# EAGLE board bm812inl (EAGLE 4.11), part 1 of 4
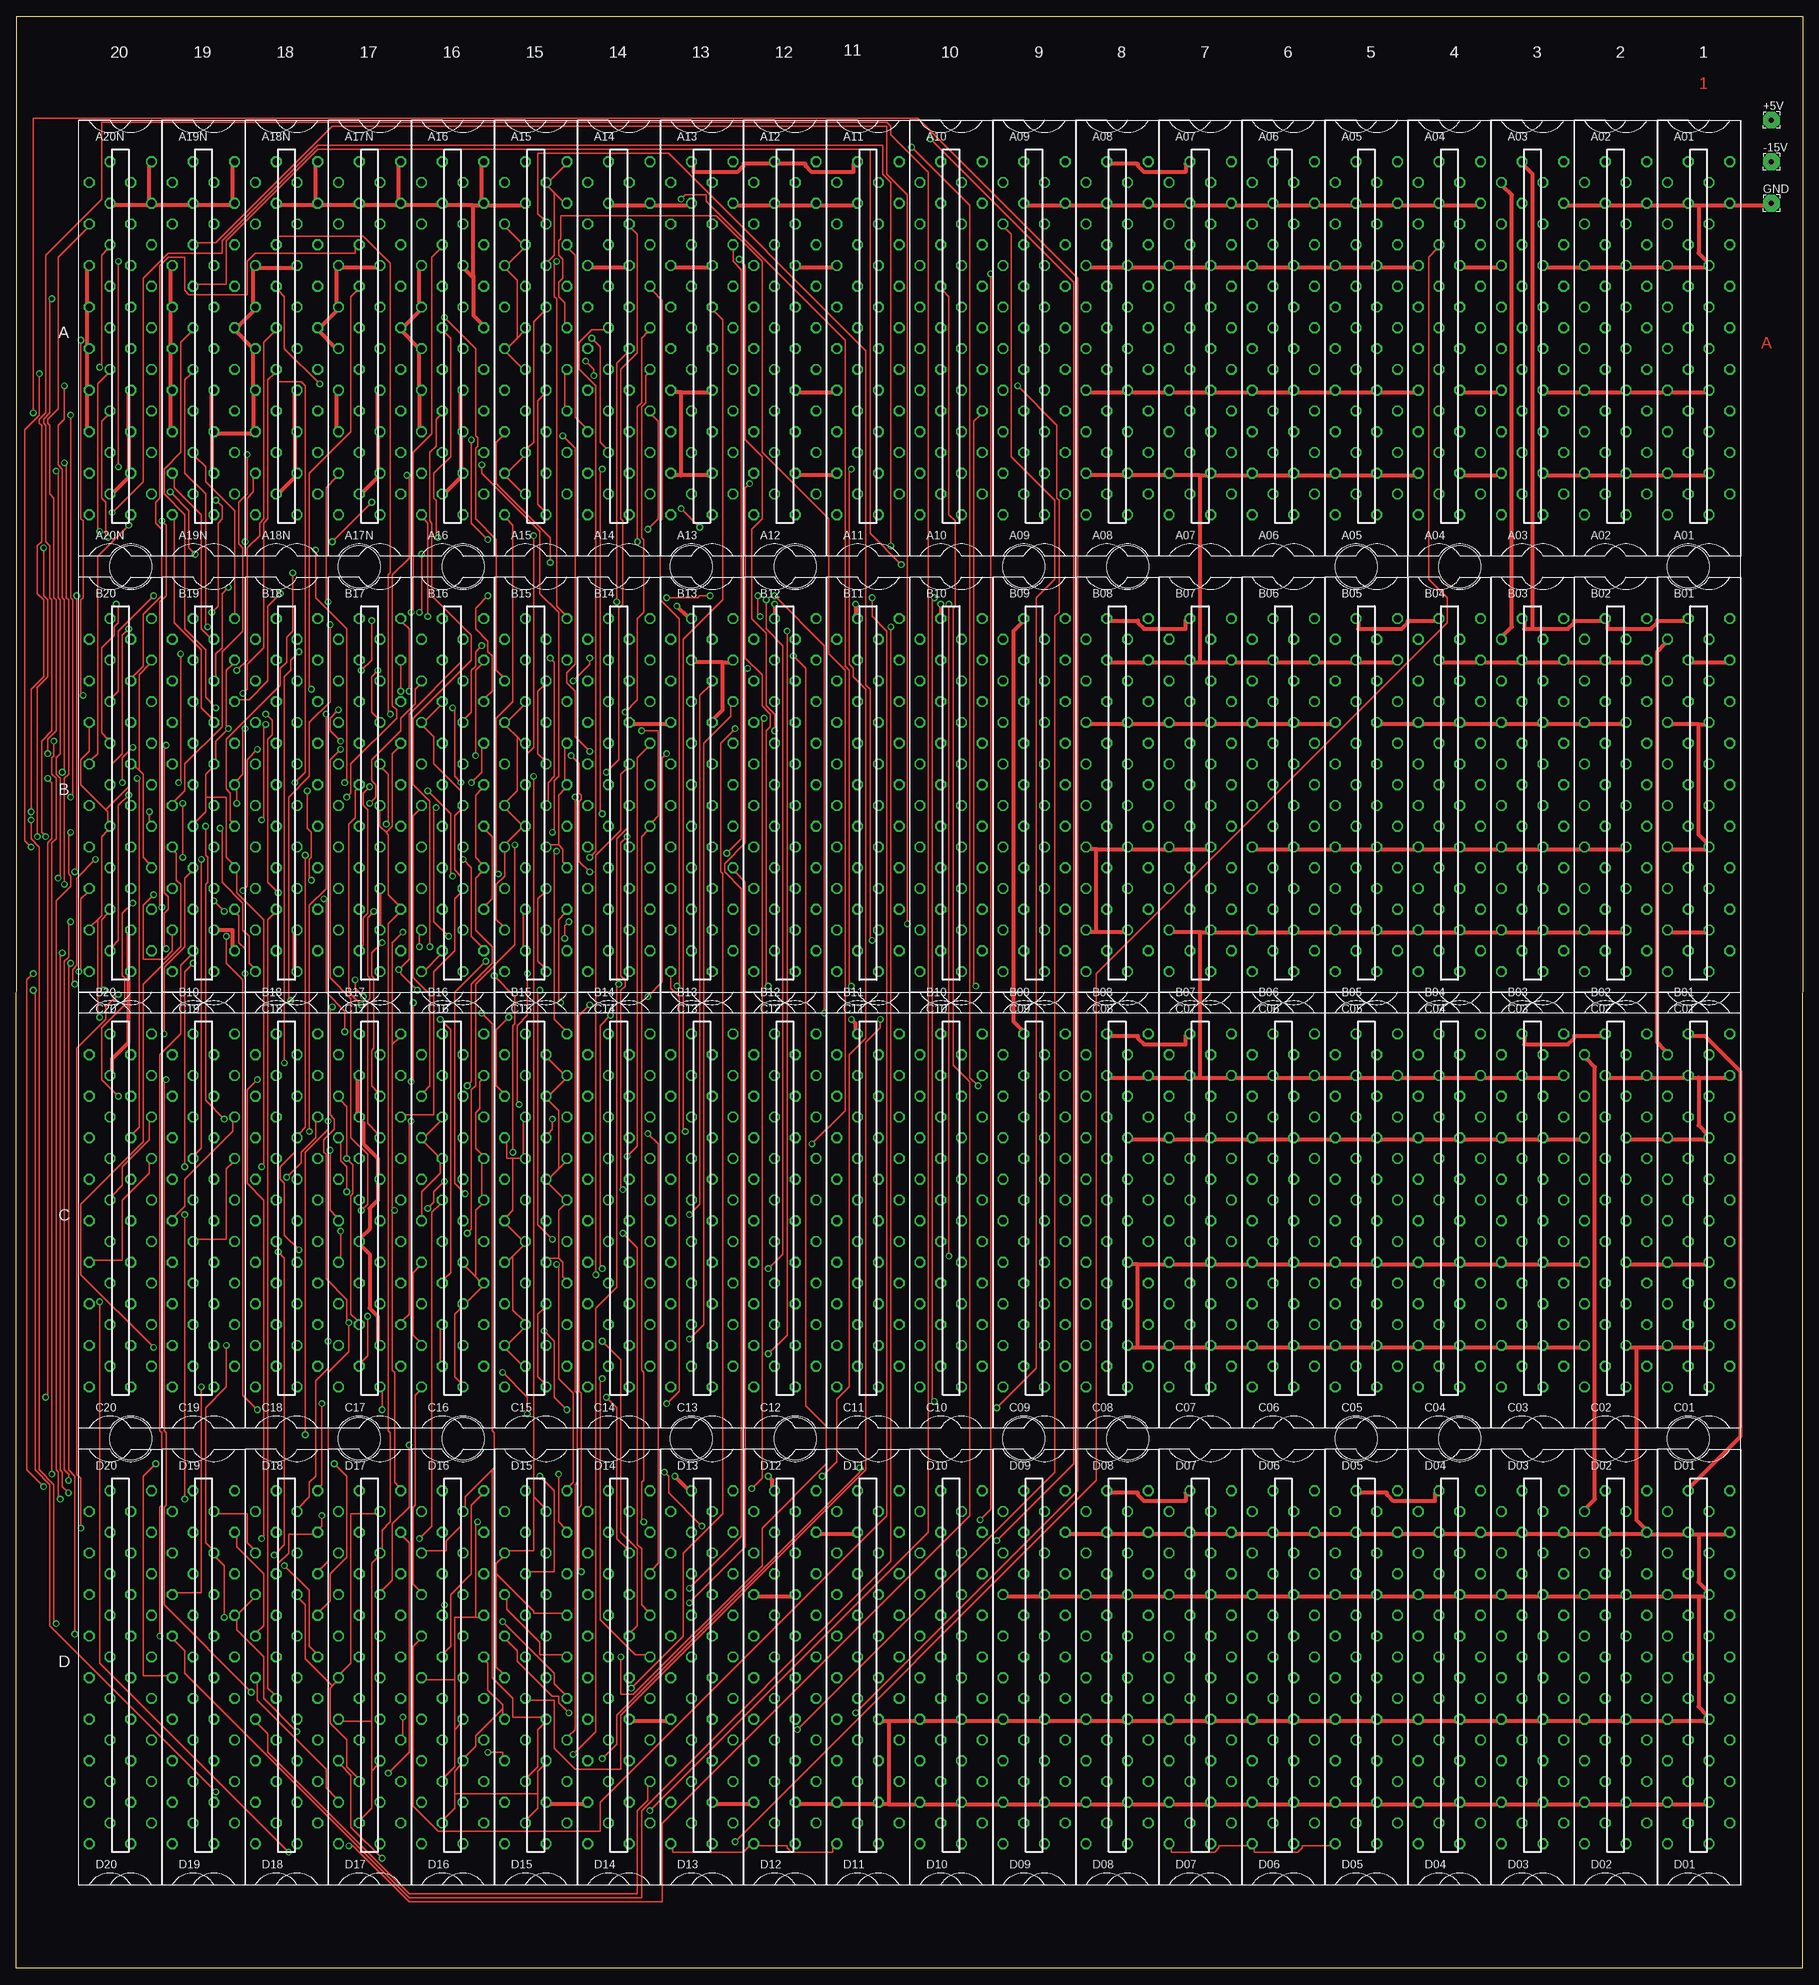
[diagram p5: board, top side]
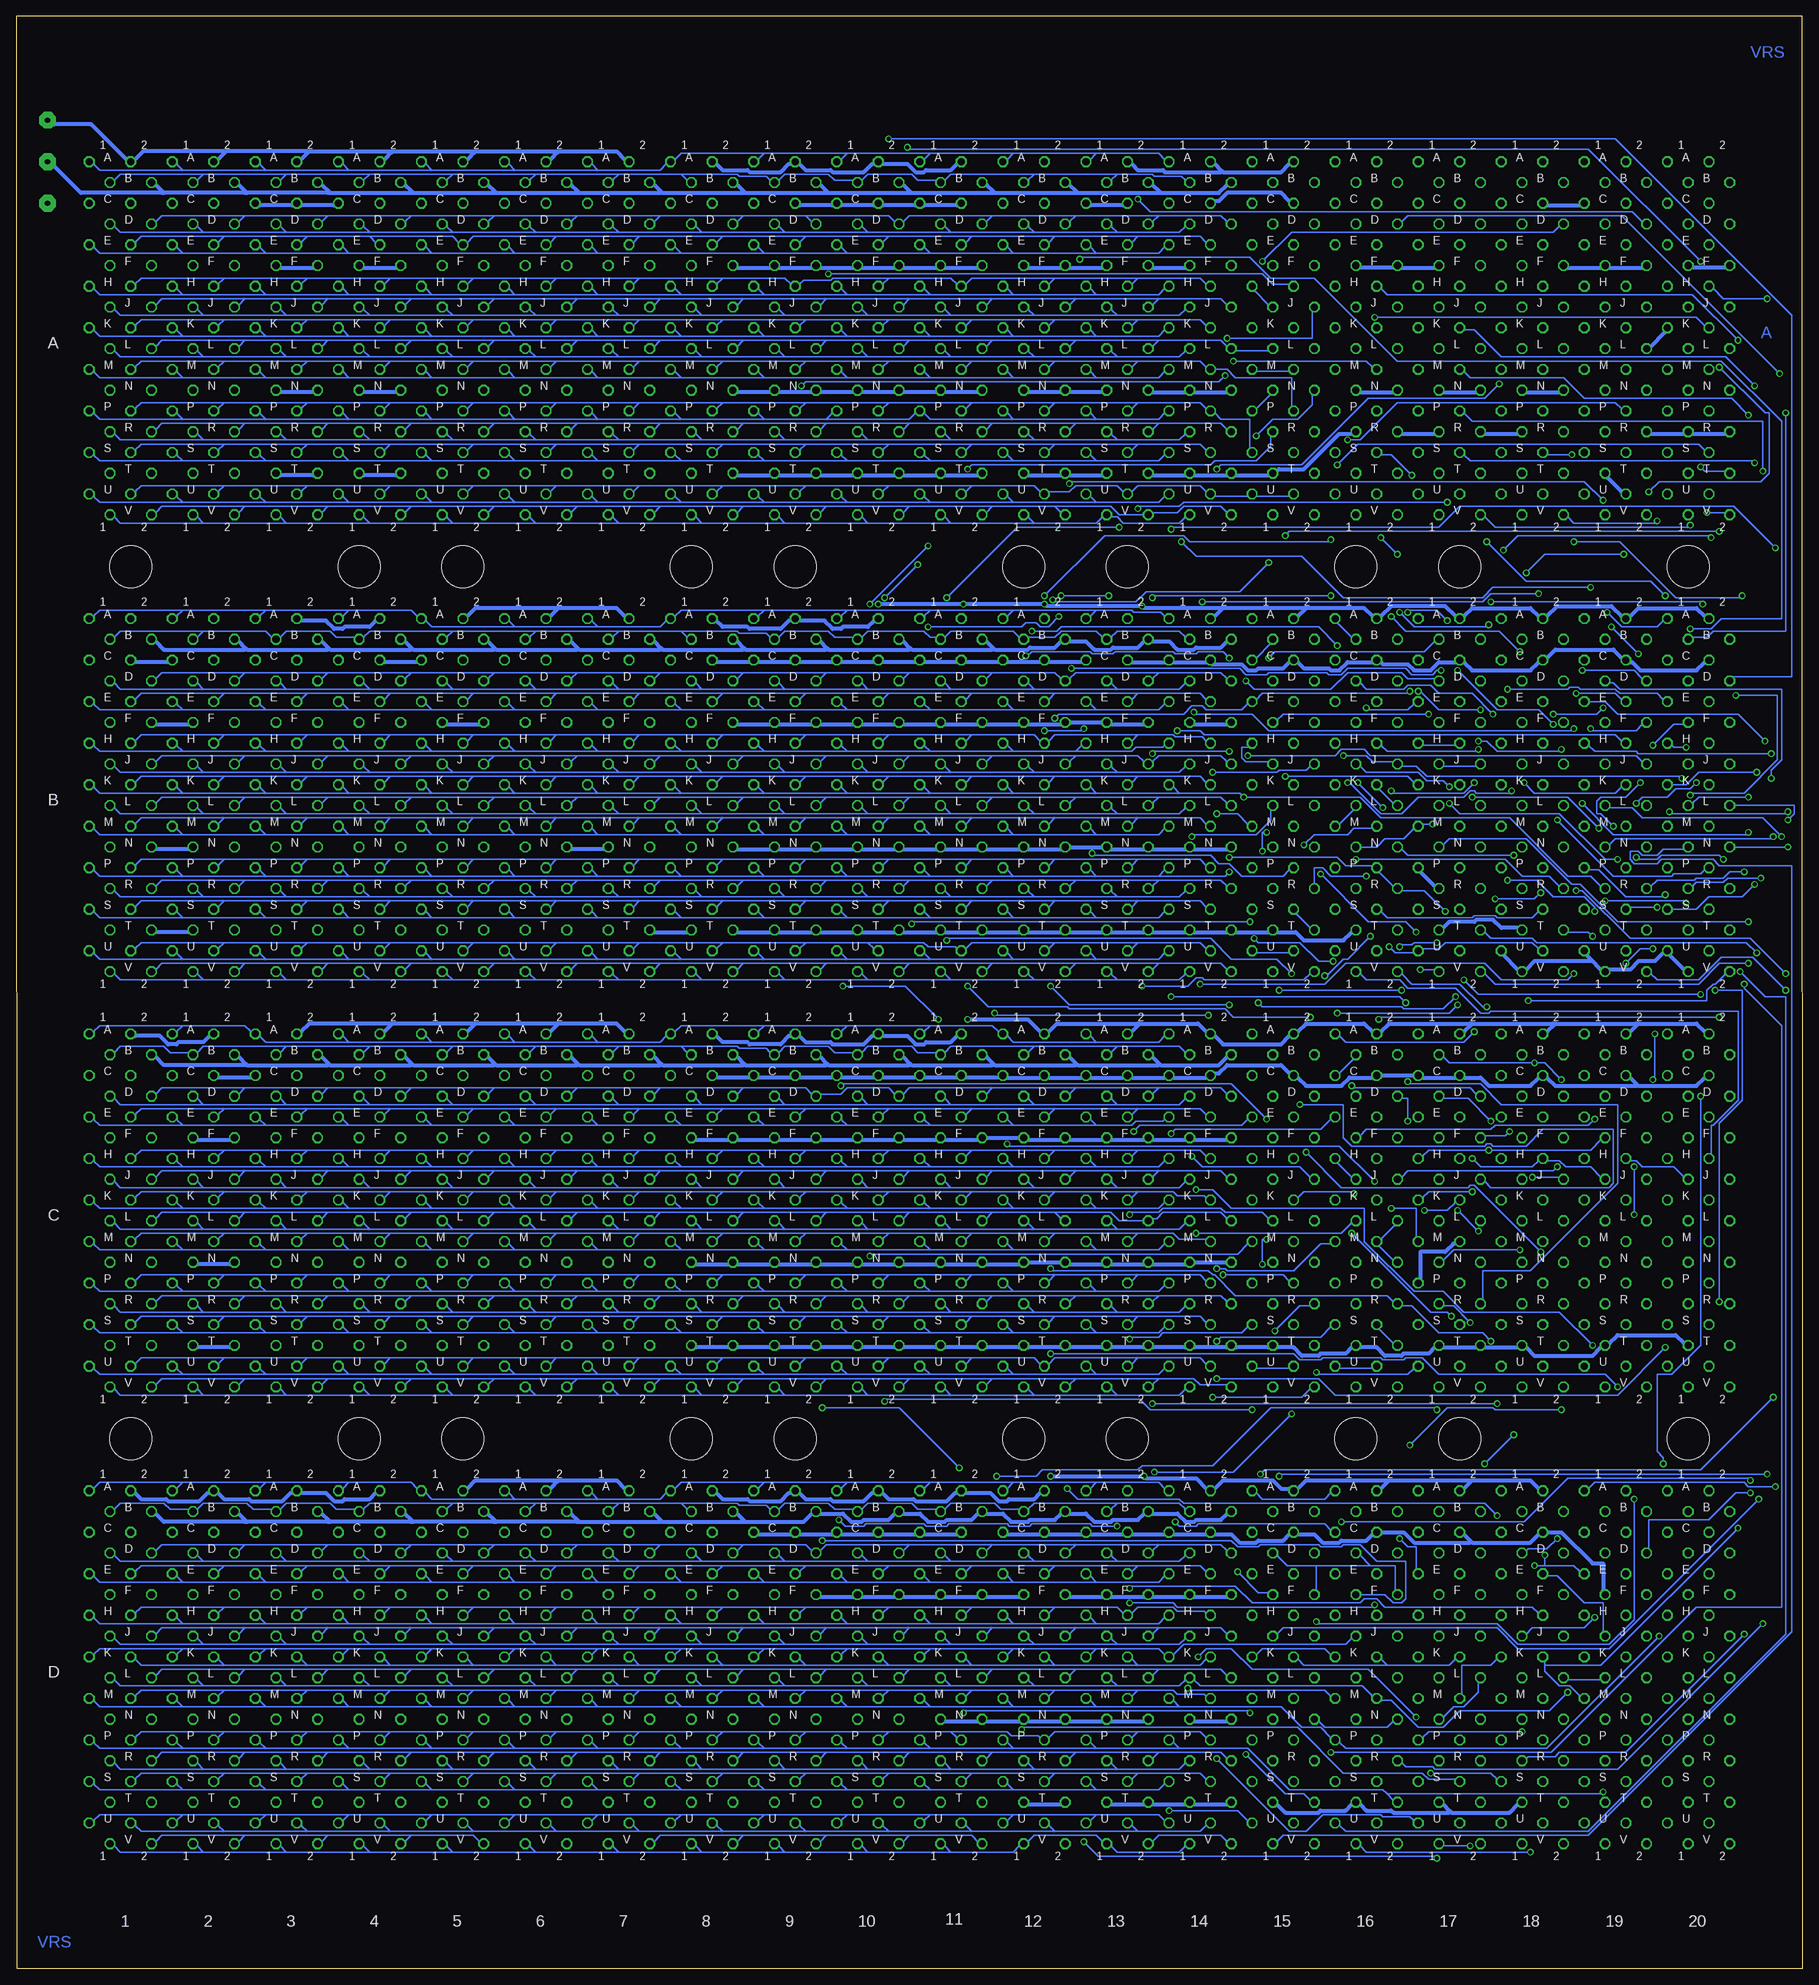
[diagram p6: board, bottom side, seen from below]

Size 273.11 x 298.44 mm. Coordinates in mm from the lower left corner, seen from the top.
Outline: 273.08,0 0,0 0.03,298.42 273.11,298.44 273.08,0
Copper layers (1*2*15*16): Top 0.035mm / dielectric 1.5mm / Route2 0.035mm / dielectric 0.15mm / Route15 0.035mm / dielectric 0.2mm / Bottom 0.035mm
Design rules "10mils": minimum track width 10mil, minimum drill 24mil, track to track 5mil, track to pad 10mil, pad to pad 10mil, via to via 5mil, smd to smd 10mil, copper to edge 40mil, drill to drill 10mil, minimum pad ring 10mil, minimum via ring 8mil, stop-mask expansion 0mil, vias tented up to drill 0mil, thermal gap 10mil
Net classes: 1 Power: width 0.635 mm

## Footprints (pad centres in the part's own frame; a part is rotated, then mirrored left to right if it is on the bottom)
2,54/0,8 = drill 0.813 pad 2.54 octagon: 1 0,0
H807 = drill 1.092 octagon: A1 4.763,28.575; A2 -1.587,28.575; B1 1.587,25.4; B2 -4.763,25.4; C1 4.763,22.225; C2 -1.587,22.225; D1 1.587,19.05; D2 -4.763,19.05; E1 4.763,15.875; E2 -1.587,15.875; F1 1.587,12.7; F2 -4.763,12.7; H1 4.763,9.525; H2 -1.587,9.525; J1 1.587,6.35; J2 -4.763,6.35; K1 4.763,3.175; K2 -1.587,3.175; L1 1.587,0; L2 -4.763,0; M1 4.763,-3.175; M2 -1.587,-3.175; N1 1.587,-6.35; N2 -4.763,-6.35; P1 4.763,-9.525; P2 -1.587,-9.525; R1 1.587,-12.7; R2 -4.763,-12.7; S1 4.763,-15.875; S2 -1.587,-15.875; T1 1.587,-19.05; T2 -4.763,-19.05; U1 4.763,-22.225; U2 -1.587,-22.225; V1 1.587,-25.4; V2 -4.763,-25.4
CBLOCK = hole 6.452: 7.938,68.263; 42.862,68.263

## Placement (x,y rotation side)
+5V  [2,54/0,8]  268.32,282.56 0 top
-15V  [2,54/0,8]  268.32,276.21 0 top
A01  [H807]  257.21,247.64 0 top
A02  [H807]  244.51,247.64 0 top
A03  [H807]  231.81,247.64 0 top
A04  [H807]  219.11,247.64 0 top
A05  [H807]  206.41,247.64 0 top
A06  [H807]  193.71,247.64 0 top
A07  [H807]  181.01,247.64 0 top
A08  [H807]  168.31,247.64 0 top
A09  [H807]  155.61,247.64 0 top
A10  [H807]  142.91,247.64 0 top
A11  [H807]  130.21,247.64 0 top
A12  [H807]  117.51,247.64 0 top
A13  [H807]  104.81,247.64 0 top
A14  [H807]  92.11,247.64 0 top
A15  [H807]  79.41,247.64 0 top
A16  M903  [H807]  66.71,247.64 0 top
A17N  M903  [H807]  54.01,247.64 0 top
A18N  M903  [H807]  41.31,247.64 0 top
A19N  M903  [H807]  28.61,247.64 0 top
A20N  M903  [H807]  15.91,247.64 0 top
B01  [H807]  257.21,177.79 0 top
B02  [H807]  244.51,177.79 0 top
B03  [H807]  231.81,177.79 0 top
B04  [H807]  219.11,177.79 0 top
B05  [H807]  206.41,177.79 0 top
B06  [H807]  193.71,177.79 0 top
B07  [H807]  181.01,177.79 0 top
B08  [H807]  168.31,177.79 0 top
B09  [H807]  155.61,177.79 0 top
B10  [H807]  142.91,177.79 0 top
B11  [H807]  130.21,177.79 0 top
B12  [H807]  117.51,177.79 0 top
B13  [H807]  104.81,177.79 0 top
B14  [H807]  92.11,177.79 0 top
B15  [H807]  79.41,177.79 0 top
B16  [H807]  66.71,177.79 0 top
B17  [H807]  54.01,177.79 0 top
B18  [H807]  41.31,177.79 0 top
B19  [H807]  28.61,177.79 0 top
B20  [H807]  15.91,177.79 0 top
C01  [H807]  257.21,114.29 0 top
C02  [H807]  244.51,114.29 0 top
C03  [H807]  231.81,114.29 0 top
C04  [H807]  219.11,114.29 0 top
C05  [H807]  206.41,114.29 0 top
C06  [H807]  193.71,114.29 0 top
C07  [H807]  181.01,114.29 0 top
C08  [H807]  168.31,114.29 0 top
C09  [H807]  155.61,114.29 0 top
C10  [H807]  142.91,114.29 0 top
C11  [H807]  130.21,114.29 0 top
C12  [H807]  117.51,114.29 0 top
C13  [H807]  104.81,114.29 0 top
C14  [H807]  92.11,114.29 0 top
C15  [H807]  79.41,114.29 0 top
C16  [H807]  66.71,114.29 0 top
C17  M206X  [H807]  54.01,114.29 0 top
C18  M310  [H807]  41.31,114.29 0 top
C19  M310  [H807]  28.61,114.29 0 top
C20  M310  [H807]  15.91,114.29 0 top
D01  [H807]  257.21,44.44 0 top
D02  [H807]  244.51,44.44 0 top
D03  [H807]  231.81,44.44 0 top
D04  [H807]  219.11,44.44 0 top
D05  [H807]  206.41,44.44 0 top
D06  [H807]  193.71,44.44 0 top
D07  [H807]  181.01,44.44 0 top
D08  [H807]  168.31,44.44 0 top
D09  [H807]  155.61,44.44 0 top
D10  [H807]  142.91,44.44 0 top
D11  [H807]  130.21,44.44 0 top
D12  [H807]  117.51,44.44 0 top
D13  [H807]  104.81,44.44 0 top
D14  [H807]  92.11,44.44 0 top
D15  M206X  [H807]  79.41,44.44 0 top
D16  M206X  [H807]  66.71,44.44 0 top
D17  M206X  [H807]  54.01,44.44 0 top
D18  [H807]  41.31,44.44 0 top
D19  M921  [H807]  28.61,44.44 0 top
D20  H807  [H807]  15.91,44.44 0 top
GND  [2,54/0,8]  268.32,269.86 0 top
U$1  [CBLOCK]  9.56,146.04 0 top
U$2  [CBLOCK]  60.36,146.04 0 top
U$3  [CBLOCK]  111.16,146.04 0 top
U$4  [CBLOCK]  161.96,146.04 0 top
U$5  [CBLOCK]  212.76,146.04 0 top
U$6  [CBLOCK]  9.56,12.69 0 top
U$7  [CBLOCK]  60.36,12.69 0 top
U$8  [CBLOCK]  111.16,12.69 0 top
U$9  [CBLOCK]  161.96,12.69 0 top
U$10  [CBLOCK]  212.76,12.69 0 top

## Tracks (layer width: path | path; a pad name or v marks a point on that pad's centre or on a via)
-15V
  Top 0.635: D02.B2 240.07,70.47 241.34,71.74 241.34,137.78 240.07,139.05 C02.B2 | B01.B2 252.13,202.55 250.86,201.28 250.86,141.59 252.13,140.32 C01.B2 | A03.B2 227.37,272.4 228.64,271.13 228.64,205.09 227.37,203.82 B03.B2
  Bottom 0.635: 98.3,271.61 99.41,272.72 A13.B2 | 98.3,271.61 98.14,271.45 89.25,271.45 87.98,272.72 A14.B2 | 111,271.61 110.84,271.45 98.46,271.45 98.3,271.61 | 111,271.61 112.11,272.72 A12.B2 | 123.7,271.61 123.54,271.45 111.16,271.45 111,271.61 | 123.7,271.61 124.81,272.72 A11.B2 | 136.4,271.61 136.24,271.45 123.86,271.45 123.7,271.61 | 136.4,271.61 137.51,272.72 A10.B2 | 149.1,271.61 148.94,271.45 136.56,271.45 136.4,271.61 | 149.1,271.61 150.21,272.72 A09.B2 | 161.8,271.61 161.64,271.45 149.26,271.45 149.1,271.61 | 161.8,271.61 162.91,272.72 A08.B2 | 174.5,271.61 174.34,271.45 161.96,271.45 161.8,271.61 | 174.5,271.61 175.61,272.72 A07.B2 | 187.2,271.61 187.04,271.45 174.66,271.45 174.5,271.61 | 187.2,271.61 188.31,272.72 A06.B2 | 199.9,271.61 199.74,271.45 187.36,271.45 187.2,271.61 | 199.9,271.61 201.01,272.72 A05.B2 | 212.6,271.61 212.44,271.45 200.06,271.45 199.9,271.61 | 212.6,271.61 213.71,272.72 A04.B2 | 225.3,271.61 225.14,271.45 212.76,271.45 212.6,271.61 | 225.3,271.61 226.41,272.72 A03.B2 | 238,271.61 237.84,271.45 225.46,271.45 225.3,271.61 | 238,271.61 239.11,272.72 A02.B2 | 250.7,271.61 250.54,271.45 238.16,271.45 238,271.61 | 250.7,271.61 251.81,272.72 A01.B2 | -15V.1 267.37,275.58 263.24,271.45 250.86,271.45 250.7,271.61 | B14.B2 87.98,202.87 88.94,201.92 92.75,201.92 93.06,201.6 95.6,201.6 96.87,202.87 99.41,202.87 B13.B2 100.68,202.87 101.64,201.92 105.45,201.92 105.76,201.6 108.3,201.6 109.57,202.87 112.11,202.87 B12.B2 113.38,202.87 114.34,201.92 118.15,201.92 118.46,201.6 123.54,201.6 123.7,201.76 | 123.7,201.76 124.81,202.87 B11.B2 | 136.4,201.76 136.24,201.6 123.86,201.6 123.7,201.76
  Bottom 0.635: 136.4,201.76 137.51,202.87 B10.B2 | 149.1,201.76 148.94,201.6 136.56,201.6 136.4,201.76 | 149.1,201.76 150.21,202.87 B09.B2 | 161.8,201.76 161.64,201.6 149.26,201.6 149.1,201.76 | 161.8,201.76 162.91,202.87 B08.B2 | 174.5,201.76 174.34,201.6 161.96,201.6 161.8,201.76 | 174.5,201.76 175.61,202.87 B07.B2 | 187.2,201.76 187.04,201.6 174.66,201.6 174.5,201.76 | 187.2,201.76 188.31,202.87 B06.B2 | 199.9,201.76 199.74,201.6 187.36,201.6 187.2,201.76 | 199.9,201.76 201.01,202.87 B05.B2 | 212.6,201.76 212.44,201.6 200.06,201.6 199.9,201.76 | 212.6,201.76 213.71,202.87 B04.B2 | 225.3,201.76 225.14,201.6 212.76,201.6 212.6,201.76 | 225.3,201.76 226.41,202.87 B03.B2 | 238,201.76 237.84,201.6 225.46,201.6 225.3,201.76 | 238,201.76 239.11,202.87 B02.B2 | B01.B2 251.81,202.87 250.54,201.6 238.16,201.6 238,201.76 | D14.B2 87.98,69.52 88.94,68.57 92.75,68.57 93.06,68.25 94.33,68.25 95.6,69.52 99.41,69.52 D13.B2 100.68,69.52 101.64,68.57 105.45,68.57 105.76,68.25 108.3,68.25 109.57,69.52 112.11,69.52 D12.B2 113.38,69.52 114.34,68.57 118.15,68.57 118.46,68.25 121,68.25 122.27,69.52 124.81,69.52 D11.B2 126.08,69.52 127.04,68.57 130.85,68.57 131.16,68.25 133.7,68.25 134.97,69.52 137.51,69.52 D10.B2 138.78,69.52 139.74,68.57 143.55,68.57 143.86,68.25 145.45,68.25 146.72,69.52 150.21,69.52 D09.B2 151.48,69.52 152.75,68.25 161.64,68.25 161.8,68.41 | 161.8,68.41 162.91,69.52 D08.B2 | 174.5,68.41 174.34,68.25 161.96,68.25 161.8,68.41 | 174.5,68.41 175.61,69.52 D07.B2 | 187.2,68.41 187.04,68.25 174.66,68.25 174.5,68.41 | 187.2,68.41 188.31,69.52 D06.B2 | 199.9,68.41 199.74,68.25 187.36,68.25 187.2,68.41
  Bottom 0.635: 199.9,68.41 201.01,69.52 D05.B2 | 212.6,68.41 212.44,68.25 200.06,68.25 199.9,68.41 | 212.6,68.41 213.71,69.52 D04.B2 | 225.3,68.41 225.14,68.25 212.76,68.25 212.6,68.41 | 225.3,68.41 226.41,69.52 D03.B2 | 238,68.41 237.84,68.25 225.46,68.25 225.3,68.41 | 238,68.41 239.11,69.52 D02.B2 | D01.B2 251.81,69.52 250.54,68.25 238.16,68.25 238,68.41 | 98.3,138.26 99.41,139.37 C13.B2 | 98.3,138.26 98.14,138.1 89.25,138.1 87.98,139.37 C14.B2 | 111,138.26 110.84,138.1 98.46,138.1 98.3,138.26 | 111,138.26 112.11,139.37 C12.B2 | 123.7,138.26 123.54,138.1 111.16,138.1 111,138.26 | 123.7,138.26 124.81,139.37 C11.B2 | 136.4,138.26 136.24,138.1 123.86,138.1 123.7,138.26 | 136.4,138.26 137.51,139.37 C10.B2 | 149.1,138.26 148.94,138.1 136.56,138.1 136.4,138.26 | 149.1,138.26 150.21,139.37 C09.B2 | 161.8,138.26 161.64,138.1 149.26,138.1 149.1,138.26 | 161.8,138.26 162.91,139.37 C08.B2 | 174.5,138.26 174.34,138.1 161.96,138.1 161.8,138.26 | 174.5,138.26 175.61,139.37 C07.B2 | 187.2,138.26 187.04,138.1 174.66,138.1 174.5,138.26 | 187.2,138.26 188.31,139.37 C06.B2 | 199.9,138.26 199.74,138.1 187.36,138.1 187.2,138.26 | 199.9,138.26 201.01,139.37 C05.B2 | 212.6,138.26 212.44,138.1 200.06,138.1 199.9,138.26 | 212.6,138.26 213.71,139.37 C04.B2 | 225.3,138.26 225.14,138.1 212.76,138.1 212.6,138.26 | 225.3,138.26 226.41,139.37 C03.B2 | 238,138.26 237.84,138.1 225.46,138.1 225.3,138.26 | 238,138.26 239.11,139.37 C02.B2 | C01.B2 251.81,139.37 250.54,138.1 238.16,138.1 238,138.26
A15U1
  Top 0.254: 82.27,271.45 83.54,270.18 A15.C1 | 82.27,271.45 81.32,272.4 A15.B1 81.63,273.36 83.86,275.58 A15.A1 | 82.27,271.45 82.27,261.93 81.32,260.97 A15.F1 80.68,259.7 80.68,254.62 A15.J1 80.68,253.35 79.09,251.77 79.09,233.35 78.14,232.4 A15.S2 77.51,231.13 75.28,228.9 A15.T2 74.97,227.95 77.19,225.73 A15.U2
  Bottom 0.254: A15.J1 81.63,254.3 83.86,256.53 A15.H1 | A15.U2 78.46,225.09 83.54,225.09 A15.U1 84.81,225.09 89.89,225.09 A14.U2 91.16,225.73 92.11,226.68 101.64,226.68 102.59,225.73 A13.U2 103.86,225.73 104.81,226.68 111.16,226.68 112.11,225.73 115.29,225.73 A12.U2 116.56,225.73 117.51,226.68 127.04,226.68 | 127.04,226.68 127.99,225.73 A11.U2 | 139.74,226.68 140.69,225.73 A10.U2 | 127.04,226.68 139.74,226.68 | 152.44,226.68 153.39,225.73 A09.U2 | 139.74,226.68 152.44,226.68 | 165.14,226.68 166.09,225.73 A08.U2 | 152.44,226.68 165.14,226.68 | 177.84,226.68 178.79,225.73 A07.U2 | 165.14,226.68 177.84,226.68 | 190.54,226.68 191.49,225.73 A06.U2 | 177.84,226.68 190.54,226.68 | 203.24,226.68 204.19,225.73 A05.U2 | 190.54,226.68 203.24,226.68 | 215.94,226.68 216.89,225.73 A04.U2 | 203.24,226.68 215.94,226.68 | 228.64,226.68 229.59,225.73 A03.U2 | 215.94,226.68 228.64,226.68 | 241.34,226.68 242.29,225.73 A02.U2 | 228.64,226.68 241.34,226.68 | 241.34,226.68 254.04,226.68 254.99,225.73 A01.U2
A15V1
  Top 0.254: A15.D2 74.97,266.05 77.19,263.83 A15.E2 77.51,262.88 75.28,260.66 A15.F2 74.97,259.7 76.55,258.11 76.55,249.23 | A15.M2 77.19,244.78 74.97,247 A15.L2 75.28,247.96 76.55,249.23 | 76.55,249.23 77.51,250.18 A15.K2 | A15.V1 80.68,222.87 79.73,223.83 79.73,239.7 80.68,240.65 A15.N1 | A15.M1 83.86,243.83 83.86,238.75 A15.P1
  Bottom 0.254: A15.P1 83.54,238.43 81.32,240.65 A15.N1 | A15.M2 78.46,244.14 83.54,244.14 A15.M1
B17S1
  Top 0.254: 56.55,173.66 55.6,174.61 B17.L1 | 56.55,173.66 56.87,173.34 56.87,164.14 58.46,162.55 B17.S1 58.46,161.28 56.87,159.69 56.87,82.22 57.19,81.9 57.19,68.25 55.92,66.98 55.92,64.12 D17.D1 55.28,62.85 54.33,61.9 54.33,37.77 | 56.55,173.66 57.5,174.61 57.5,185.73 58.46,186.68 B17.H1 | 54.33,30.15 54.33,24.44 52.74,22.85 D17.U2 | 54.33,30.15 55.28,31.1 D17.R1 | 54.33,37.77 49.88,37.77 D17.N2 | 54.33,30.15 54.33,37.77
  Bottom 0.254: B17.H2 53.06,186.99 58.14,186.99 B17.H1
B17V1  (via drill 0.61)
  Top 0.254: D16.A1 71.16,72.38 69.57,70.79 69.57,60.31 66.39,57.14 66.39,49.2 65.44,48.25 D16.K2 | B16.B1 67.98,202.55 67.98,199.7 60.04,191.76 60.04,154.29 v58.46,152.71 58.77,152.39 58.77,152.07 v61.31,149.53 | v82.59,107.62 82.9,107.3 82.9,90.16 85.13,87.94 85.13,74.28 84.49,73.65 D15.A1 | v81.95,111.43 79.73,113.65 79.73,149.21 v80.05,149.53
  Bottom 0.254: D16.A1 72.11,72.69 73.06,71.74 82.59,71.74 83.54,72.69 D15.A1 | 63.54,46.34 54.01,46.34 53.06,47.29 D17.K2 | 63.54,46.34 64.49,47.29 D16.K2 | 63.54,46.34 76.24,46.34 77.19,47.29 D15.K2 | v58.46,152.71 56.23,152.71 B17.V1 | B16.A1 71.16,205.73 68.93,203.51 B16.B1 | v82.59,107.62 82.59,111.43 v81.95,111.43 | v61.31,149.53 v80.05,149.53
C16U1
  Top 0.254: C16.U2 64.81,92.7 64.81,97.78 C16.S2 | C16.E2 64.81,129.53 62.58,127.3 C16.F2 62.27,126.35 64.49,124.13 C16.H2 64.81,123.18 64.81,121.59 61.95,118.73 C16.L2 | C16.T2 61.63,95.87 60.68,96.83 60.68,106.35 61.63,107.3 C16.N2
  Bottom 0.254: C16.U2 65.76,91.74 70.84,91.74 C16.U1 | C16.T2 62.58,95.55 64.81,97.78 C16.S2 | C16.N2 62.58,108.25 64.81,110.48 C16.M2 64.49,111.43 62.27,113.65 C16.L2
D01BINIT  (via drill 0.61)
  Top 0.254: v47.66,95.87 47.66,91.74 45.76,89.84 45.76,75.24 44.8,74.28 44.8,72.06 43.22,70.47 D18.B1 | v81.63,214.93 81.63,218.74 73.38,227 73.38,233.35 74.33,234.3 A15.R2 | v114.65,209.22 114.65,204.77 117.19,202.24 117.19,109.21 v114.97,106.99
  Bottom 0.254: v47.66,95.87 48.93,97.14 55.6,97.14 59.73,101.27 61.31,101.27 C16.R2 62.58,101.91 63.54,102.86 86.71,102.86 89.89,106.03 90.21,106.03 90.84,106.67 114.65,106.67 v114.97,106.99 | v81.63,214.93 86.08,210.49 100.37,210.49 101.95,208.9 114.34,208.9 v114.65,209.22
D01BTP2L  (via drill 0.61)
  Top 0.254: B16.V2 62.58,152.71 64.81,154.93 B16.U2 | D18.E1 46.39,60.95 47.66,62.22 47.66,91.11 50.84,94.28 v50.84,98.73 50.52,99.05 50.52,102.22 47.34,105.4 47.34,124.45 47.03,124.77 47.03,126.67 48.61,128.26 48.61,129.84 47.98,130.48 47.98,146.67 v48.3,146.99
  Bottom 0.254: v50.84,98.73 53.38,101.27 54.96,101.27 C17.R1 | v48.3,146.99 48.93,146.99 52.42,150.48 59.73,150.48 61.31,152.07 B16.V2
D01DEL1H  (via drill 0.61)
  Top 0.254: v18.45,181.92 18.77,181.6 18.77,128.58 17.82,127.62 C20.F1 | v70.2,185.41 70.2,198.43 71.16,199.38 B16.C1
  Bottom 0.254: v18.45,181.92 18.77,182.23 57.5,182.23 59.09,183.82 61.31,183.82 B16.J2 62.58,184.46 65.76,184.46 66.71,185.41 v70.2,185.41
D01DEL1L  (via drill 0.61)
  Top 0.254: v50.52,118.73 50.52,122.54 49.57,123.49 49.57,126.35 C17.F2 | v47.34,191.76 47.34,165.09 44.8,162.55 v44.8,127.94
  Bottom 0.254: v50.52,118.73 57.19,118.73 58.14,117.78 C17.K1 | v47.34,191.76 50.52,194.93 55.6,194.93 56.87,196.2 60.36,196.2 61,195.57 66.71,195.57 67.66,196.52 B16.D1 | v44.8,127.94 45.44,127.3 48.61,127.3 C17.F2
D01DEL2  (via drill 0.61)
  Top 0.254: v54.01,178.11 54.96,179.06 54.96,180.96 54.33,181.6 54.33,184.77 58.77,189.22 58.77,191.12 61,193.34 61,195.57 61.63,196.2 B16.D2 | v28.29,169.53 28.29,125.4 27.34,124.45 C19.H2
  Bottom 0.254: C20.J1 18.13,120.96 19.72,122.54 24.48,122.54 25.44,123.49 26.39,123.49 C19.H2 | v54.01,178.11 52.42,176.52 37.18,176.52 30.2,169.53 v28.29,169.53
D01DEL3  (via drill 0.61)
  Top 0.254: v47.98,125.08 47.98,115.88 48.93,114.92 C17.L2
  Bottom 0.254: C19.F1 30.83,126.67 32.42,125.08 v47.98,125.08 57.19,125.08 58.14,124.13 C17.H1
D01DEL4  (via drill 0.61)
  Top 0.254: B16.K1 71.16,180.33 70.2,179.37 70.2,169.85 71.16,168.9 B16.P1 71.16,167.63 70.2,166.68 70.2,158.74 72.74,156.2 72.74,153.66 69.57,150.48 69.57,135.56 v68.93,134.93 | C17.S2 52.11,99.05 51.15,100 51.15,118.1 51.47,118.41 51.47,122.86 v50.52,123.81 50.52,131.75 49.57,132.7 C17.D2
  Bottom 0.254: C19.J1 30.83,120.96 32.42,122.54 36.23,122.54 37.18,123.49 39.09,123.49 C18.H2 40.36,123.49 41.31,122.54 49.25,122.54 v50.52,123.81 | v68.93,134.93 68.62,134.61 50.84,134.61 49.88,133.65 C17.D2
D01DEL5  (via drill 0.61)
  Top 0.254: v43.22,109.84 40.99,112.07 40.99,120 40.36,120.64 40.36,122.54 42.58,124.77 42.58,126.35 C18.F1 43.22,127.62 44.17,128.58 v44.17,170.17
  Bottom 0.254: v43.22,109.84 53.38,109.84 54.96,108.25 C17.N1 | v44.17,170.17 60.36,170.17 61.31,171.12 B16.N2
D01DONEH
  Top 0.254: D18.N2 36.87,37.45 38.45,35.86 38.45,33.01 60.04,11.42 94.97,11.42 94.97,24.12 96.56,25.71 96.56,27.93 D14.S1
  Bottom 0.254: 107.99,27.29 98.46,27.29 97.51,28.25 D14.S1 | 107.99,27.29 108.94,28.25 D13.S1 | 120.69,27.29 121.64,28.25 D12.S1 | 120.69,27.29 107.99,27.29 | 133.39,27.29 134.34,28.25 D11.S1 | 133.39,27.29 120.69,27.29 | 146.09,27.29 147.04,28.25 D10.S1 | 146.09,27.29 133.39,27.29 | 158.79,27.29 159.74,28.25 D09.S1 | 158.79,27.29 146.09,27.29 | 171.49,27.29 172.44,28.25 D08.S1 | 171.49,27.29 158.79,27.29 | 184.19,27.29 185.14,28.25 D07.S1 | 184.19,27.29 171.49,27.29 | 196.89,27.29 197.84,28.25 D06.S1 | 196.89,27.29 184.19,27.29 | 209.59,27.29 210.54,28.25 D05.S1 | 209.59,27.29 196.89,27.29 | 222.29,27.29 223.24,28.25 D04.S1 | 222.29,27.29 209.59,27.29 | 234.99,27.29 235.94,28.25 D03.S1 | 234.99,27.29 222.29,27.29 | 247.69,27.29 248.64,28.25 D02.S1 | 234.99,27.29 247.69,27.29 | 247.69,27.29 260.39,27.29 261.34,28.25 D01.S1
D01DONEL
  Top 0.254: D18.M2 39.41,41.9 38.45,42.85 38.45,160.33 39.41,161.28 B18.S2
  Bottom 0.254: B16.S2 64.49,161.59 63.54,160.64 50.52,160.64 50.2,160.96 47.03,160.96 46.71,160.64 41.31,160.64 40.36,161.59 B18.S2
D01INHIBIT
  Bottom 0.254: A15.S1 84.49,232.4 84.49,236.84 88.94,236.84 89.89,237.8 A14.P2 91.16,238.43 92.11,239.38 101.64,239.38 | 101.64,239.38 102.59,238.43 A13.P2 | 114.34,239.38 115.29,238.43 A12.P2 | 101.64,239.38 114.34,239.38 | 127.04,239.38 127.99,238.43 A11.P2 | 114.34,239.38 127.04,239.38 | 139.74,239.38 140.69,238.43 A10.P2 | 127.04,239.38 139.74,239.38 | 152.44,239.38 153.39,238.43 A09.P2 | 139.74,239.38 152.44,239.38 | 165.14,239.38 166.09,238.43 A08.P2 | 152.44,239.38 165.14,239.38 | 177.84,239.38 178.79,238.43 A07.P2 | 165.14,239.38 177.84,239.38 | 190.54,239.38 191.49,238.43 A06.P2 | 177.84,239.38 190.54,239.38 | 203.24,239.38 204.19,238.43 A05.P2 | 190.54,239.38 203.24,239.38 | 215.94,239.38 216.89,238.43 A04.P2 | 203.24,239.38 215.94,239.38 | 228.64,239.38 229.59,238.43 A03.P2 | 215.94,239.38 228.64,239.38 | 241.34,239.38 242.29,238.43 A02.P2 | 228.64,239.38 241.34,239.38 | 241.34,239.38 254.04,239.38 254.99,238.43 A01.P2
D01INITL  (via drill 0.61)
  Top 0.254: 57.5,141.27 57.5,116.19 v57.82,115.88 57.5,115.56 57.5,91.43 57.82,91.11 57.82,74.28 58.46,73.65 D17.A1 | 57.5,141.27 58.46,142.23 C17.A1 | v73.7,167.31 73.38,167.63 73.38,191.12 75.92,193.66 75.92,220.65 74.97,221.6 A15.V2 | v59.09,158.42 57.5,156.83 57.5,141.27
  Bottom 0.254: v57.82,115.88 54.33,115.88 53.06,117.14 C17.K2 | v73.7,167.31 66.39,160.01 60.68,160.01 v59.09,158.42
D01LOADMDL  (via drill 0.61)
  Top 0.254: v56.55,174.93 56.87,175.25 56.87,182.55 55.92,183.5 B17.J1
  Bottom 0.254: B17.J2 49.88,183.82 54.96,183.82 B17.J1 | B16.N1 65.12,171.44 63.85,172.71 61,172.71 59.41,174.3 B17.M1 58.14,174.93 v56.55,174.93
D01MEMDONEL  (via drill 0.61)
  Top 0.254: v31.15,174.3 31.47,173.98 31.47,166.04 34.64,162.86 34.64,158.74 35.6,157.79 35.6,153.66 36.23,153.02 B18.V2 | v50.52,179.06 51.15,179.69 51.15,184.14 58.14,191.12 58.14,192.39 57.5,193.03 57.5,213.03 60.04,215.57 60.04,227.95 v59.73,228.27
  Bottom 0.254: v31.15,174.3 35.91,179.06 v50.52,179.06 | v59.73,228.27 62.9,231.45 64.49,231.45 A16.S2
D01MEMSTARTL  (via drill 0.61)
  Top 0.254: v48.61,77.14 50.52,75.24 50.52,62.85 47.98,60.31 47.98,56.18 46.39,54.6 D18.H1 | v44.17,81.58 44.17,124.77 47.66,128.26 v47.66,129.53 | v61.63,156.2 61.63,158.1 B16.T2 | v55.92,156.83 54.33,155.24 54.33,151.75 54.65,151.43 54.65,140.64 54.33,140.32 54.33,134.93 55.28,133.97 C17.D1
  Bottom 0.254: v48.61,77.14 v44.17,81.58 | v47.66,129.53 51.15,133.02 54.96,133.02 C17.D1 | v61.63,156.2 61.31,156.52 59.73,156.52 59.41,156.83 v55.92,156.83
D01POWEROK  (via drill 0.61)
  Top 0.254: v46.71,86.35 46.71,73.97 46.39,73.65 D18.A1 | v99.41,86.35 101.32,88.25 101.32,148.58 100.05,149.85 B13.V2
  Bottom 0.254: v99.41,86.35 v46.71,86.35 | 98.46,153.66 88.94,153.66 87.98,152.71 B14.V2 | 98.46,153.66 99.41,152.71 B13.V2 | 111.16,153.66 112.11,152.71 B12.V2 | 111.16,153.66 98.46,153.66 | 123.86,153.66 124.81,152.71 B11.V2 | 111.16,153.66 123.86,153.66 | 136.56,153.66 137.51,152.71 B10.V2 | 123.86,153.66 136.56,153.66 | 149.26,153.66 150.21,152.71 B09.V2 | 136.56,153.66 149.26,153.66 | 161.96,153.66 162.91,152.71 B08.V2 | 149.26,153.66 161.96,153.66 | 174.66,153.66 175.61,152.71 B07.V2 | 161.96,153.66 174.66,153.66 | 187.36,153.66 188.31,152.71 B06.V2 | 174.66,153.66 187.36,153.66 | 200.06,153.66 201.01,152.71 B05.V2 | 187.36,153.66 200.06,153.66 | 212.76,153.66 213.71,152.71 B04.V2 | 200.06,153.66 212.76,153.66 | 225.46,153.66 226.41,152.71 B03.V2 | 212.76,153.66 225.46,153.66 | 238.16,153.66 239.11,152.71 B02.V2 | 225.46,153.66 238.16,153.66 | 238.16,153.66 250.86,153.66 251.81,152.71 B01.V2
D01READH
  Top 0.254: B16.E2 64.81,193.03 62.58,190.8 B16.F2 62.27,189.85 63.85,188.27 63.85,184.14 67.98,180.01 67.98,178.42 B16.L1 67.98,177.15 67.03,176.2 67.03,167.95 67.98,166.99 67.98,165.72 B16.R1 67.98,164.45 67.03,163.5 67.03,155.56 63.85,152.39 63.85,130.48 59.41,130.48 C17.E1 | B16.S1 71.79,162.55 72.74,163.5 72.74,173.02 71.79,173.98 B16.M1
  Bottom 0.254: B16.L1 68.62,177.15 70.84,174.93 B16.M1
D01READL  (via drill 0.61)
  Top 0.254: v54.65,161.59 53.69,160.64 53.69,151.75 54.01,151.43 54.01,148.26 53.69,147.94 53.69,129.21 55.28,127.62 C17.F1 | v87.67,169.85 88.62,170.8 88.62,241.92 86.08,244.46 86.08,248.59 87.98,250.49 89.89,250.49 A14.K2
  Bottom 0.254: v54.65,161.59 57.82,164.77 61.31,164.77 B16.R2 62.58,165.4 64.81,167.63 B16.P2 65.76,168.58 69.89,168.58 71.16,169.85 v87.67,169.85 | 101.64,252.08 92.11,252.08 91.16,251.13 A14.K2 | 101.64,252.08 102.59,251.13 A13.K2 | 114.34,252.08 115.29,251.13 A12.K2 | 101.64,252.08 114.34,252.08 | 127.04,252.08 127.99,251.13 A11.K2 | 114.34,252.08 127.04,252.08 | 139.74,252.08 140.69,251.13 A10.K2 | 127.04,252.08 139.74,252.08 | 152.44,252.08 153.39,251.13 A09.K2 | 139.74,252.08 152.44,252.08 | 165.14,252.08 166.09,251.13 A08.K2 | 152.44,252.08 165.14,252.08 | 177.84,252.08 178.79,251.13 A07.K2 | 165.14,252.08 177.84,252.08 | 190.54,252.08 191.49,251.13 A06.K2 | 177.84,252.08 190.54,252.08 | 203.24,252.08 204.19,251.13 A05.K2 | 190.54,252.08 203.24,252.08 | 215.94,252.08 216.89,251.13 A04.K2 | 203.24,252.08 215.94,252.08 | 228.64,252.08 229.59,251.13 A03.K2 | 215.94,252.08 228.64,252.08 | 241.34,252.08 242.29,251.13 A02.K2 | 228.64,252.08 241.34,252.08 | 241.34,252.08 254.04,252.08 254.99,251.13 A01.K2
D01RETURN
  Top 0.254: A15.E1 84.49,262.88 85.44,261.93 85.44,237.16 87.03,235.57 A14.R2
  Bottom 0.254: 98.46,236.21 88.94,236.21 87.98,235.26 A14.R2 | 98.46,236.21 99.41,235.26 A13.R2 | 111.16,236.21 112.11,235.26 A12.R2 | 98.46,236.21 111.16,236.21 | 123.86,236.21 124.81,235.26 A11.R2 | 111.16,236.21 123.86,236.21 | 136.56,236.21 137.51,235.26 A10.R2 | 123.86,236.21 136.56,236.21 | 149.26,236.21 150.21,235.26 A09.R2 | 136.56,236.21 149.26,236.21 | 161.96,236.21 162.91,235.26 A08.R2 | 149.26,236.21 161.96,236.21 | 174.66,236.21 175.61,235.26 A07.R2 | 161.96,236.21 174.66,236.21 | 187.36,236.21 188.31,235.26 A06.R2 | 174.66,236.21 187.36,236.21 | 200.06,236.21 201.01,235.26 A05.R2 | 187.36,236.21 200.06,236.21 | 212.76,236.21 213.71,235.26 A04.R2 | 200.06,236.21 212.76,236.21 | 225.46,236.21 226.41,235.26 A03.R2 | 212.76,236.21 225.46,236.21 | 238.16,236.21 239.11,235.26 A02.R2 | 225.46,236.21 238.16,236.21 | 238.16,236.21 250.86,236.21 251.81,235.26 A01.R2
D01SELECTH  (via drill 0.61)
  Top 0.254: v61.63,65.71 63.54,67.61 63.54,115.56 64.81,116.83 C16.K2
  Bottom 0.254: v61.63,65.71 60.36,64.44 59.09,64.44 59.09,60.95 D17.E1
D01SELECTL  (via drill 0.61)
  Top 0.254: v60.04,80 60.04,70.47 57.5,67.93 57.5,59.36 55.92,57.77 D17.F1 | v36.87,85.39 34.64,87.62 34.64,151.12 32.1,153.66 v32.1,157.79
  Bottom 0.254: v60.04,80 54.33,85.71 47.34,85.71 47.03,85.39 v36.87,85.39 | v32.1,157.79 32.74,158.42 35.91,158.42 B18.T2
D01SELH  (via drill 0.61)
  Top 0.254: v56.87,29.83 60.04,33.01 60.04,65.08 59.09,66.03 D17.C1
  Bottom 0.254: v56.87,29.83 47.66,29.83 46.71,28.88 D18.S1
D01SELL  (via drill 0.61)
  Top 0.254: v8.93,51.1 8.93,75.24 7.97,76.19 7.97,153.34 v8.29,153.66
  Bottom 0.254: v8.93,51.1 27.02,33.01 37.18,33.01 37.82,32.37 41.95,32.37 42.26,32.06 D18.R1 | v8.29,153.66 12.74,153.66 15.91,150.48 47.03,150.48 48.61,152.07 B17.V2
D01SOURCE
  Bottom 0.254: A15.L1 81.63,247.32 86.71,247.32 A14.L2 87.98,247.96 88.94,248.91 98.46,248.91 | 98.46,248.91 99.41,247.96 A13.L2 | 111.16,248.91 112.11,247.96 A12.L2 | 98.46,248.91 111.16,248.91 | 123.86,248.91 124.81,247.96 A11.L2 | 111.16,248.91 123.86,248.91 | 136.56,248.91 137.51,247.96 A10.L2 | 123.86,248.91 136.56,248.91 | 149.26,248.91 150.21,247.96 A09.L2 | 136.56,248.91 149.26,248.91 | 161.96,248.91 162.91,247.96 A08.L2 | 149.26,248.91 161.96,248.91 | 174.66,248.91 175.61,247.96 A07.L2 | 161.96,248.91 174.66,248.91 | 187.36,248.91 188.31,247.96 A06.L2 | 174.66,248.91 187.36,248.91 | 200.06,248.91 201.01,247.96 A05.L2 | 187.36,248.91 200.06,248.91 | 212.76,248.91 213.71,247.96 A04.L2 | 200.06,248.91 212.76,248.91 | 225.46,248.91 226.41,247.96 A03.L2 | 212.76,248.91 225.46,248.91 | 238.16,248.91 239.11,247.96 A02.L2 | 225.46,248.91 238.16,248.91 | 238.16,248.91 250.86,248.91 251.81,247.96 A01.L2
D01STROBE
  Bottom 0.254: A15.P2 78.14,238.75 78.14,243.19 86.71,243.19 87.98,244.46 A14.M2 91.16,244.78 92.11,245.73 101.64,245.73 | 101.64,245.73 102.59,244.78 A13.M2 | 114.34,245.73 115.29,244.78 A12.M2 | 101.64,245.73 114.34,245.73 | 127.04,245.73 127.99,244.78 A11.M2 | 114.34,245.73 127.04,245.73 | 139.74,245.73 140.69,244.78 A10.M2 | 127.04,245.73 139.74,245.73 | 152.44,245.73 153.39,244.78 A09.M2 | 139.74,245.73 152.44,245.73 | 165.14,245.73 166.09,244.78 A08.M2 | 152.44,245.73 165.14,245.73 | 177.84,245.73 178.79,244.78 A07.M2 | 165.14,245.73 177.84,245.73 | 190.54,245.73 191.49,244.78 A06.M2 | 177.84,245.73 190.54,245.73 | 203.24,245.73 204.19,244.78 A05.M2 | 190.54,245.73 203.24,245.73 | 215.94,245.73 216.89,244.78 A04.M2 | 203.24,245.73 215.94,245.73 | 228.64,245.73 229.59,244.78 A03.M2 | 215.94,245.73 228.64,245.73 | 241.34,245.73 242.29,244.78 A02.M2 | 228.64,245.73 241.34,245.73 | 241.34,245.73 254.04,245.73 254.99,244.78 A01.M2
D01STROBEL  (via drill 0.61)
  Top 0.254: v63.22,156.2 63.22,178.42 60.68,180.96 60.68,191.12 69.57,200.01 69.57,203.82 63.54,209.86 63.54,220.97 63.22,221.29 63.22,231.76 64.17,232.71 64.17,236.84 64.81,237.48 A16.P2
  Bottom 0.254: B18.U2 40.36,155.88 41.31,156.83 54.65,156.83 55.6,155.88 58.14,155.88 B17.U1 59.41,155.24 62.27,155.24 v63.22,156.2
D01WRITE  (via drill 0.61)
  Top 0.254: v87.98,249.23 89.25,247.96 89.25,233.35 90.21,232.4 A14.S2
  Bottom 0.254: 101.64,233.03 92.11,233.03 91.16,232.08 A14.S2 | 101.64,233.03 102.59,232.08 A13.S2 | 114.34,233.03 115.29,232.08 A12.S2 | 101.64,233.03 114.34,233.03 | 127.04,233.03 127.99,232.08 A11.S2 | 114.34,233.03 127.04,233.03 | 139.74,233.03 140.69,232.08 A10.S2 | 127.04,233.03 139.74,233.03 | 152.44,233.03 153.39,232.08 A09.S2 | 139.74,233.03 152.44,233.03 | 165.14,233.03 166.09,232.08 A08.S2 | 152.44,233.03 165.14,233.03 | 177.84,233.03 178.79,232.08 A07.S2 | 165.14,233.03 177.84,233.03 | 190.54,233.03 191.49,232.08 A06.S2 | 177.84,233.03 190.54,233.03 | 203.24,233.03 204.19,232.08 A05.S2 | 190.54,233.03 203.24,233.03 | 215.94,233.03 216.89,232.08 A04.S2 | 203.24,233.03 215.94,233.03 | 228.64,233.03 229.59,232.08 A03.S2 | 215.94,233.03 228.64,233.03 | 241.34,233.03 242.29,232.08 A02.S2 | 228.64,233.03 241.34,233.03 | 241.34,233.03 254.04,233.03 254.99,232.08 A01.S2 | v87.98,249.23 74.97,249.23 74.97,253.35 A15.J2
D01WRITEH  (via drill 0.61)
  Top 0.254: v60.36,129.53 60.04,129.21 60.04,100 59.09,99.05 C17.S1 | B16.L2 61.63,177.15 60.68,176.2 60.68,151.43 63.22,148.89 63.22,134.93 62.27,133.97 C16.D2
  Bottom 0.254: B16.L2 62.58,178.11 64.81,180.33 B16.K2 | v60.36,129.53 60.36,133.02 61.31,133.02 C16.D2
D02MEM0
  Top 0.254: B20.D1 17.82,197.47 19.4,199.06 19.4,207 22.26,209.86 22.26,220.02 21.31,220.97 21.31,224.14 21.94,224.78 21.94,260.34 23.21,261.61 25.75,261.61 25.75,256.53 26.39,255.89 35.28,255.89 35.28,260.97 36.55,262.24 51.79,262.24 51.79,263.19 A17N.E2
D02MEM1  (via drill 0.61)
  Top 0.254: v45.12,195.57 44.8,195.89 44.8,228.59 51.15,234.94 51.15,255.58 52.11,256.53 A17N.H2
  Bottom 0.254: v45.12,195.57 35.91,195.57 35.6,195.89 34.33,195.89 34.01,195.57 28.61,195.57 27.98,194.93 22.26,194.93 21.31,193.98 B20.E1
D02MEM2  (via drill 0.61)
  Top 0.254: v7.02,182.87 7.34,183.18 7.34,209.22 7.02,209.54 7.02,229.22 6.39,229.86 6.39,235.89 7.34,236.84 v7.34,241.92
  Bottom 0.254: v7.02,182.87 15.91,182.87 17.82,180.96 B20.K1 | v7.34,241.92 11.78,246.37 46.07,246.37 50.2,250.49 51.79,250.49 A17N.K2
D02MEM3  (via drill 0.61)
  Top 0.254: v8.29,179.06 8.61,179.37 8.61,209.22 8.29,209.54 v8.29,237.48
  Bottom 0.254: v8.29,179.06 15.91,179.06 16.86,178.11 B20.L1 | v8.29,237.48 10.83,240.02 33.37,240.02 36.55,243.19 50.84,243.19 51.79,244.14 A17N.M2
D02MEM4  (via drill 0.61)
  Top 0.254: v6.39,166.68 6.7,166.99 6.7,181.92 6.07,182.55 6.07,185.09 6.7,185.73 6.7,209.22 6.39,209.54 6.39,228.59 v6.07,228.9
  Bottom 0.254: v6.39,166.68 11.47,166.68 12.1,166.04 16.23,166.04 16.86,165.4 B20.R1 | v6.07,228.9 6.07,236.52 50.52,236.52 51.79,237.8 A17N.P2
D02MEM5  (via drill 0.61)
  Top 0.254: v7.34,165.72 7.34,181.92 7.97,182.55 7.97,209.22 7.66,209.54 7.66,229.86 v7.34,230.18
  Bottom 0.254: v7.34,165.72 9.24,163.82 14.32,163.82 16.23,161.91 B20.S1 | v7.34,230.18 7.66,230.49 50.84,230.49 51.79,231.45 A17N.S2
D02MEM6  (via drill 0.61)
  Top 0.254: v15.28,208.58 15.59,208.27 15.59,205.73 14.96,205.09 14.96,203.82 13.05,201.92 13.05,188.9 14.01,187.95 B20.H2 | v47.66,208.9 47.34,209.22 47.34,226.36 48.93,227.95 A17N.T2
  Bottom 0.254: v15.28,208.58 15.59,208.9 v47.66,208.9
D02MEM7  (via drill 0.61)
  Top 0.254: v17.18,220.65 12.42,215.89 12.42,185.73 11.47,184.77 B20.J2
  Bottom 0.254: v17.18,220.65 17.5,220.33 47.03,220.33 48.61,221.92 A17N.V2
D02MEM8  (via drill 0.61)
  Top 0.254: v2.26,171.44 1.31,172.39 1.31,235.26 3.53,237.48 v3.53,243.83
  Bottom 0.254: v3.53,243.83 27.66,267.96 60.36,267.96 61.31,267 A16.D2 | v2.26,171.44 B20.N2
D02MEM9  (via drill 0.61)
  Top 0.254: v37.5,175.56 37.82,175.88 37.82,189.85 v38.14,190.17 | v52.74,198.43 54.33,200.01 v54.33,206.05 | v60.36,207.31 60.68,207.63 60.68,231.76 63.54,234.62 63.54,261.61 64.81,262.88 A16.E2
  Bottom 0.254: v37.5,175.56 28.93,166.99 20.04,166.99 19.72,167.31 15.59,167.31 14.96,167.95 B20.P2 | v38.14,190.17 40.36,192.39 46.71,192.39 v52.74,198.43 | v54.33,206.05 55.92,207.63 60.04,207.63 v60.36,207.31
D02MEM10  (via drill 0.61)
  Top 0.254: v17.18,179.37 15.59,177.79 15.59,157.15 14.64,156.2 B20.U2 | v10.2,194.61 9.88,194.93 9.88,209.22 10.2,209.54 10.2,221.29 9.88,221.6 v9.88,248.91
  Bottom 0.254: v17.18,179.37 16.86,179.69 8.93,179.69 3.85,184.77 3.85,194.61 v10.2,194.61 | v9.88,248.91 16.86,255.89 63.54,255.89 64.49,256.85 A16.H2
D02MEM11  (via drill 0.61)
  Top 0.254: v41.95,147.94 41.63,148.26 41.63,179.06 44.8,182.23 44.8,190.49 47.98,193.66 v47.98,205.41 | v61.63,207.31 61.95,207.63 v61.95,216.21 | v64.49,218.74 64.17,219.06 64.17,224.46 63.85,224.78 63.85,228.59 66.39,231.13 66.39,249.23 65.44,250.18 A16.K2
  Bottom 0.254: v41.95,147.94 14.64,147.94 14.64,149.53 13.69,150.48 13.37,150.48 11.78,152.07 B20.V2 | v47.98,205.41 48.3,205.09 59.41,205.09 v61.63,207.31 | v61.95,216.21 v64.49,218.74
D03BEMA0L  (via drill 0.61)
  Top 0.254: v89.57,32.06 91.79,34.28 91.79,38.72 128.94,75.87 v128.94,76.5 | v149.9,85.71 155.93,91.74 155.93,209.54 158.79,212.39 158.79,224.46 152.12,231.13 152.12,265.1 151.17,266.05 A09.D2
  Bottom 0.254: 98.46,267.96 88.94,267.96 87.98,267 A14.D2 | 98.46,267.96 99.41,267 A13.D2 | 111.16,267.96 112.11,267 A12.D2 | 111.16,267.96 98.46,267.96 | 123.86,267.96 124.81,267 A11.D2 | 123.86,267.96 111.16,267.96 | 123.86,267.96 136.56,267.96 137.51,267 A10.D2 138.78,267 139.74,267.96 152.44,267.96 | v89.57,32.06 78.46,20.94 75.92,20.94 73.38,23.48 64.49,23.48 64.17,23.16 60.04,23.16 59.41,22.53 D17.U1 | v128.94,76.5 138.15,85.71 v149.9,85.71 | 161.96,267.96 162.91,267 A08.D2 | 161.96,267.96 152.44,267.96 | 152.44,267.96 151.48,267 A09.D2 | 174.66,267.96 175.61,267 A07.D2 | 174.66,267.96 161.96,267.96 | 187.36,267.96 188.31,267 A06.D2 | 187.36,267.96 174.66,267.96 | 200.06,267.96 201.01,267 A05.D2 | 200.06,267.96 187.36,267.96 | 212.76,267.96 213.71,267 A04.D2 | 212.76,267.96 200.06,267.96 | 225.46,267.96 226.41,267 A03.D2 | 225.46,267.96 212.76,267.96 | 238.16,267.96 239.11,267 A02.D2 | 238.16,267.96 225.46,267.96 | 238.16,267.96 250.86,267.96 251.81,267 A01.D2
D03BEMA1L  (via drill 0.61)
  Top 0.254: v55.92,16.82 51.15,21.58 51.15,29.51 49.57,31.1 D17.R2 | v109.89,19.35 165.14,74.6 165.14,152.07 218.79,205.73 218.79,209.54 215.94,212.39 215.94,261.61 217.21,262.88 A04.E2
  Bottom 0.254: 101.64,264.78 92.11,264.78 91.16,263.83 A14.E2 | 101.64,264.78 102.59,263.83 A13.E2 | 114.34,264.78 115.29,263.83 A12.E2 | 114.34,264.78 101.64,264.78 | 127.04,264.78 127.99,263.83 A11.E2 | 127.04,264.78 114.34,264.78 | 139.74,264.78 140.69,263.83 A10.E2 | 139.74,264.78 127.04,264.78 | 152.44,264.78 153.39,263.83 A09.E2 | 152.44,264.78 139.74,264.78 | 165.14,264.78 166.09,263.83 A08.E2 | 165.14,264.78 152.44,264.78 | 177.84,264.78 178.79,263.83 A07.E2 | 177.84,264.78 165.14,264.78 | 190.54,264.78 191.49,263.83 A06.E2 | 190.54,264.78 177.84,264.78 | 190.54,264.78 203.24,264.78 204.19,263.83 A05.E2 205.46,263.83 206.41,264.78 219.11,264.78 | v55.92,16.82 56.23,17.13 107.67,17.13 v109.89,19.35 | 228.64,264.78 229.59,263.83 A03.E2 | 228.64,264.78 219.11,264.78 | 219.11,264.78 218.16,263.83 A04.E2 | 241.34,264.78 242.29,263.83 A02.E2 | 241.34,264.78 228.64,264.78 | 241.34,264.78 254.04,264.78 254.99,263.83 A01.E2
D03BEMA2L  (via drill 0.61)
  Top 0.254: v50.84,18.72 51.47,18.72 60.04,10.15 98.78,10.15 98.78,22.21 145.77,69.2 145.77,135.56 143.23,138.1 143.23,207.95 143.55,208.27 143.55,221.29 142.59,222.24 142.59,255.58 141.64,256.53 A10.H2
  Bottom 0.254: 165.14,258.43 155.61,258.43 154.66,257.48 A09.H2 153.39,257.48 152.75,258.11 148.63,258.11 148.31,258.43 139.74,258.43 | 165.14,258.43 166.09,257.48 A08.H2 | 177.84,258.43 178.79,257.48 A07.H2 | 177.84,258.43 165.14,258.43 | 190.54,258.43 191.49,257.48 A06.H2 | 190.54,258.43 177.84,258.43 | 203.24,258.43 204.19,257.48 A05.H2 | 203.24,258.43 190.54,258.43 | 215.94,258.43 216.89,257.48 A04.H2 | 215.94,258.43 203.24,258.43 | 228.64,258.43 229.59,257.48 A03.H2 | 228.64,258.43 215.94,258.43 | 241.34,258.43 242.29,257.48 A02.H2 | 241.34,258.43 228.64,258.43 | 241.34,258.43 254.04,258.43 254.99,257.48 A01.H2 | 101.64,258.43 92.11,258.43 91.16,257.48 A14.H2 | 101.64,258.43 102.59,257.48 A13.H2 | 114.34,258.43 115.29,257.48 A12.H2 | 114.34,258.43 101.64,258.43 | 114.34,258.43 127.04,258.43 127.99,257.48 A11.H2 129.26,257.48 130.21,258.43 139.74,258.43 | v50.84,18.72 54.96,18.72 D17.V1 | 139.74,258.43 140.69,257.48 A10.H2
D03BMA0  (via drill 0.61)
  Top 0.254: v65.44,252.4 70.2,247.64 70.2,234.3 70.52,233.99 70.52,232.71 70.2,232.4 70.2,221.6 73.38,218.43 73.38,198.43 74.33,197.47 B15.D2
  Bottom 0.254: v65.44,252.4 16.23,252.4 14.96,251.13 A20N.K2
D03BMA1  (via drill 0.61)
  Top 0.254: v79.09,219.06 79.09,186.68 78.14,185.73 78.14,181.6 B15.K2 | v12.74,219.7 12.42,220.02 12.42,242.24 14.01,243.83 A20N.M2
  Bottom 0.254: v79.09,219.06 78.46,219.7 v12.74,219.7
D03BMA2  (via drill 0.61)
  Top 0.254: v66.71,166.99 66.39,167.31 66.39,176.52 v62.9,180.01 | v50.2,181.28 50.52,181.6 50.52,204.77 45.76,209.54 v45.76,216.84 | v14.01,218.74 13.69,219.06 13.69,224.14 13.05,224.78 13.05,236.52 14.01,237.48 A20N.P2
  Bottom 0.254: v66.71,166.99 72.11,166.99 73.38,168.26 74.65,168.26 B15.R2 | v62.9,180.01 62.58,179.69 51.79,179.69 v50.2,181.28 | v45.76,216.84 43.53,219.06 14.32,219.06 v14.01,218.74
D03BMA3  (via drill 0.61)
  Top 0.254: v82.59,170.8 82.27,170.49 82.27,145.08 83.86,143.5 C15.A1 | v81.95,173.66 82.27,173.98 82.27,181.6 82.9,182.23 82.9,207.31 80.05,210.17 80.05,219.7 71.16,228.59 v71.16,229.86
  Bottom 0.254: v82.59,170.8 82.59,173.66 v81.95,173.66 | v71.16,229.86 67.98,233.03 15.91,233.03 14.96,232.08 A20N.S2
D03BMA4  (via drill 0.61)
  Top 0.254: v81.95,129.84 81.95,128.26 81.32,127.62 C15.F1 | v147.04,134.93 145.77,136.2 145.77,269.55 v136.88,278.43 | v15.59,260.97 v15.59,229.54
  Bottom 0.254: v81.95,129.84 87.35,135.24 146.72,135.24 v147.04,134.93 | v136.88,278.43 136.56,278.12 32.74,278.12 v15.59,260.97 | v15.59,229.54 14.96,228.9 11.78,228.9 A20N.T2
D03BMA5  (via drill 0.61)
  Top 0.254: v14.64,222.55 19.4,227.32 19.4,258.43 23.21,262.24 31.47,262.24 31.47,264.15 46.07,278.75 132.43,278.75 132.43,274.31 133.7,273.04 v133.7,217.48 | v142.59,208.58 v142.59,108.89
  Bottom 0.254: v14.64,222.55 11.78,222.55 A20N.V2 | v133.7,217.48 v142.59,208.58 | v142.59,108.89 142.28,109.21 86.4,109.21 84.81,110.8 C15.M1
D03BMA6  (via drill 0.61)
  Top 0.254: v101.64,270.5 102.27,271.13 105.45,271.13 105.45,270.18 126.72,248.91 126.72,199.06 127.35,198.43 127.35,150.48 v127.67,150.17 | v75.28,145.4 73.38,143.5 73.38,134.93 74.33,133.97 C15.D2
  Bottom 0.254: v101.64,270.5 99.73,268.59 26.07,268.59 24.48,267 A19N.D2 | v127.67,150.17 124.5,146.99 112.43,146.99 112.11,146.67 88.3,146.67 87.03,145.4 v75.28,145.4
D03BMA7  (via drill 0.61)
  Top 0.254: v136.24,159.69 136.24,271.13 133.07,274.31 133.07,281.61 48.3,281.61 30.52,263.83 27.66,263.83 A19N.E2 | v84.49,160.01 83.86,159.37 v83.86,157.47 | v71.79,153.98 67.03,149.21 67.03,120 v68.62,118.41
  Bottom 0.254: v136.24,159.69 135.93,160.01 v84.49,160.01 | v83.86,157.47 83.22,156.83 76.87,156.83 74.01,153.98 v71.79,153.98 | v68.62,118.41 68.93,118.73 76.24,118.73 77.19,117.78 C15.K2
D03BMA8  (via drill 0.61)
  Top 0.254: v135.29,214.62 130.53,219.38 130.53,278.12 46.07,278.12 32.1,264.15 32.1,257.48 27.66,257.48 A19N.H2 | v140.37,209.54 140.05,209.22 140.05,86.98 v140.37,86.66 | v84.17,85.39 82.27,87.3 82.27,95.87 v80.68,97.46
  Bottom 0.254: v135.29,214.62 v140.37,209.54 | v140.37,86.66 140.05,86.98 101.32,86.98 99.73,85.39 v84.17,85.39 | v80.68,97.46 76.87,101.27 75.28,101.27 C15.R2
D03BMA9  (via drill 0.61)
  Top 0.254: v30.52,192.71 28.93,194.3 28.93,201.6 25.75,204.77 25.75,222.24 22.58,225.41 22.58,229.22 25.12,231.76 25.12,248.59 26.71,250.18 A19N.K2 | v38.14,191.76 39.09,190.8 39.09,188.58 38.45,187.95 38.45,166.04 v40.04,164.45 | v47.03,163.5 47.34,163.18 47.34,149.21 50.2,146.36 v50.2,143.18
  Bottom 0.254: v30.52,192.71 31.47,191.76 v38.14,191.76 | v40.04,164.45 40.99,163.5 v47.03,163.5 | v50.2,143.18 51.79,141.59 69.89,141.59 70.84,142.55 C16.A1
D03BMA10  (via drill 0.61)
  Top 0.254: v29.25,205.09 28.93,205.41 28.93,225.41 25.75,228.59 25.75,242.87 26.71,243.83 A19N.M2 | v25.12,200.96 25.12,181.6 v24.8,181.28 | v28.93,174.61 28.93,170.17 29.25,169.85 29.25,166.04 28.93,165.72 28.93,132.7 v31.79,129.84
  Bottom 0.254: v29.25,205.09 v25.12,200.96 | v24.8,181.28 27.02,179.06 30.83,179.06 31.47,178.42 31.47,176.52 30.83,176.52 v28.93,174.61 | v31.79,129.84 32.74,128.89 47.03,128.89 47.66,128.26 66.71,128.26 67.66,127.3 C16.F1
D03BMA11  (via drill 0.61)
  Top 0.254: v69.57,233.67 69.57,220.97 v72.11,218.43 | v115.92,209.86 123.54,202.24 v123.54,146.04 | v90.84,145.72 89.25,144.13 89.25,107.3 v89.57,106.99
  Bottom 0.254: v69.57,233.67 67.66,233.67 61.95,239.38 28.61,239.38 27.66,238.43 A19N.P2 | v72.11,218.43 72.43,218.11 93.7,218.11 94.65,219.06 106.72,219.06 v115.92,209.86 | v123.54,146.04 123.23,145.72 v90.84,145.72 | v89.57,106.99 88.3,106.99 87.98,106.67 77.82,106.67 73.7,110.8 72.11,110.8 C16.M1
D03BTP2  (via drill 0.61)
  Top 0.254: v37.5,65.71 37.82,66.03 37.82,117.46 35.28,120 35.28,134.29 v36.87,135.88 | v62.9,206.68 62.9,220.97 62.27,221.6 A16.V2 | v43.22,201.28 41.95,200.01 41.95,198.43 40.99,197.47 v40.99,138.42
  Bottom 0.254: v37.5,65.71 39.09,64.12 41.95,64.12 42.26,63.81 D18.D1 | v36.87,135.88 39.41,138.42 v40.99,138.42 54.01,138.42 54.96,139.37 C17.B1 | v62.9,206.68 60.68,204.46 46.39,204.46 v43.22,201.28
D03EA0  (via drill 0.61)
  Top 0.254: v82.59,260.97 82.27,260.66 82.27,255.58 82.59,255.26 82.59,208.27 83.86,207 B15.A1
  Bottom 0.254: v82.59,260.97 78.14,265.42 38.14,265.42 37.18,266.37 A18N.D2
D03EA1  (via drill 0.61)
  Top 0.254: v57.19,191.76 56.87,192.08 56.87,213.03 57.19,213.35 57.19,260.66 53.06,264.78 40.04,264.78 40.04,264.15 A18N.E2
  Bottom 0.254: v57.19,191.76 79.41,191.76 80.36,190.8 B15.F1
D03EA2  (via drill 0.61)
  Top 0.254: v89.57,176.52 89.25,176.83 89.25,228.9 v89.57,229.22 | v46.39,242.24 40.99,247.64 40.99,255.58 40.04,256.53 A18N.H2
  Bottom 0.254: v89.57,176.52 86.4,176.52 84.81,174.93 B15.M1 | v89.57,229.22 88.94,229.86 76.55,229.86 66.39,240.02 48.61,240.02 v46.39,242.24
D03EMA0H  (via drill 0.61)
  Top 0.254: D18.F2 36.23,56.5 34.01,54.28 D19.H1 33.69,53.33 33.69,51.74 37.82,47.61 37.82,41.26 v42.9,36.18 | v85.13,196.84 87.67,199.38 v87.67,200.33 | v118.78,200.65 120.69,198.74 120.69,86.03 123.86,82.86 123.86,77.14 114.02,67.3 114.02,61.58 94.33,41.9 92.43,41.9 v92.43,47.61 | v59.09,38.4 59.09,35.55 D17.P1
  Bottom 0.254: v42.9,36.18 57.19,36.18 58.14,35.23 D17.P1 | v85.13,196.84 83.86,195.57 72.11,195.57 69.57,198.11 61.31,198.11 60.36,197.15 56.23,197.15 B17.D1 | v87.67,200.33 88.62,201.28 92.43,201.28 92.75,200.96 95.92,200.96 96.24,201.28 105.13,201.28 105.45,200.96 108.62,200.96 108.94,201.28 117.83,201.28 118.46,200.65 v118.78,200.65 | v92.43,47.61 91.16,48.88 87.35,48.88 84.17,45.71 66.39,45.71 v59.09,38.4
D03EMA0L  (via drill 0.61)
  Top 0.254: D18.E2 40.04,60.95 40.04,61.9 41.63,63.49 41.63,66.35 45.44,66.35 D18.C1 46.39,67.3 46.71,67.61 v46.71,69.2 | v60.04,195.25 60.04,204.77 59.09,205.73 B17.A1 | v112.43,73.33 114.02,74.92 114.02,190.8 v114.34,191.12
  Bottom 0.254: D19.J1 30.52,51.42 30.52,55.87 33.37,55.87 37.5,60 39.09,60 D18.E2 | v60.04,195.25 60.36,194.93 82.59,194.93 83.54,193.98 B15.E1 84.81,193.34 85.76,192.39 91.16,192.39 91.79,193.03 93.38,193.03 94.65,191.76 113.7,191.76 v114.34,191.12 | v46.71,69.2 48.61,71.11 94.65,71.11 95.29,71.74 110.84,71.74 v112.43,73.33
D03EMA1H  (via drill 0.61)
  Top 0.254: v40.99,61.58 44.8,57.77 44.8,49.2 45.76,48.25 D18.K1 | v66.71,192.71 67.03,192.39 67.03,182.23 v67.98,181.28 | v64.17,177.47 63.85,177.15 63.85,160.01 v66.08,157.79 | v73.06,151.75 76.24,148.58 76.24,144.45 75.92,144.13 v75.92,124.77 | v40.04,109.52 40.99,108.57 40.99,64.76 v39.41,63.17
  Bottom 0.254: 39.41,61.58 v40.99,61.58 | 39.41,61.58 34.96,61.58 34.01,60.63 D19.E1 | D17.M2 52.11,41.9 52.11,46.34 47.66,46.34 46.71,47.29 D18.K1 | v66.71,192.71 66.39,192.39 60.36,192.39 59.41,193.34 B17.E1 | v67.98,181.28 v64.17,177.47 | v66.08,157.79 69.57,154.29 70.2,154.29 72.74,151.75 v73.06,151.75 | v75.92,124.77 70.52,119.37 51.15,119.37 50.84,119.69 50.2,119.69 v40.04,109.52 | v39.41,63.17 39.41,61.58
D03EMA1L  (via drill 0.61)
  Top 0.254: v31.79,53.64 31.79,61.58 30.52,62.85 D19.D1 29.88,64.12 28.93,65.08 28.93,85.71 32.1,88.89 v32.1,95.24 | v81.63,200.33 82.27,199.7 82.27,182.23 81.32,181.28 81.32,178.42 B15.L1 | v92.75,119.05 92.43,119.37 92.43,149.53 93.06,150.17 93.06,151.12 92.43,151.75 92.43,172.07 v93.38,173.02
  Bottom 0.254: v31.79,53.64 33.37,52.06 41.31,52.06 42.26,51.1 D18.J1 | v81.63,200.33 80.68,201.28 57.82,201.28 56.23,202.87 B17.B1 | v32.1,95.24 37.18,100.32 51.79,100.32 54.96,103.49 59.41,103.49 67.03,111.11 67.03,116.19 87.35,116.19 90.21,119.05 v92.75,119.05 | v93.38,173.02 93.06,173.34 83.54,173.34 81.32,175.56 81.32,177.15 B15.L1
D03EMA2H
  Top 0.254: D17.T2 48.93,26.02 47.34,27.61 47.34,30.47 36.87,40.95 36.87,43.8 D18.L2
  Bottom 0.254: D19.L1 30.83,44.12 35.91,44.12 D18.L2
D03EMA2L  (via drill 0.61)
  Top 0.254: v83.22,147.62 82.9,147.94 82.9,160.33 83.86,161.28 B15.S1 | v53.06,148.58 51.79,149.85 v51.79,151.12 | v15.59,148.89 13.69,146.99 13.69,145.08 9.24,140.64 9.24,75.55 9.88,74.92 v9.88,67.3
  Bottom 0.254: 39.41,46.34 39.41,46.98 D18.K2 | 39.41,46.34 39.41,45.39 37.18,43.17 35.6,43.17 34.01,41.58 D19.M1 | v83.22,147.62 82.59,146.99 61.31,146.99 61,146.67 54.96,146.67 v53.06,148.58 | v51.79,151.12 49.57,148.89 v15.59,148.89 | v9.88,67.3 30.83,46.34 39.41,46.34
D03MA0L  (via drill 0.61)
  Top 0.254: v90.21,182.87 92.11,184.77 92.11,207.95 92.75,208.58 92.75,221.29 92.43,221.6 92.43,244.46 94.97,247 94.97,265.1 94.02,266.05 A14.D1
  Bottom 0.254: v90.21,182.87 80.36,182.87 80.05,183.18 75.92,183.18 75.28,183.82 B15.J2 | 104.81,265.42 105.76,266.37 A13.D1 | 104.81,265.42 95.29,265.42 94.33,266.37 A14.D1 | 117.51,265.42 118.46,266.37 A12.D1 | 117.51,265.42 104.81,265.42 | 130.21,265.42 131.16,266.37 A11.D1 | 130.21,265.42 117.51,265.42 | 142.91,265.42 143.86,266.37 A10.D1 | 142.91,265.42 130.21,265.42 | 155.61,265.42 156.56,266.37 A09.D1 | 155.61,265.42 142.91,265.42 | 168.31,265.42 169.26,266.37 A08.D1 | 168.31,265.42 155.61,265.42 | 181.01,265.42 181.96,266.37 A07.D1 | 181.01,265.42 168.31,265.42 | 193.71,265.42 194.66,266.37 A06.D1 | 193.71,265.42 181.01,265.42 | 206.41,265.42 207.36,266.37 A05.D1 | 206.41,265.42 193.71,265.42 | 219.11,265.42 220.06,266.37 A04.D1 | 219.11,265.42 206.41,265.42 | 231.81,265.42 232.76,266.37 A03.D1 | 231.81,265.42 219.11,265.42 | 244.51,265.42 245.46,266.37 A02.D1 | 244.51,265.42 231.81,265.42 | 244.51,265.42 257.21,265.42 258.16,266.37 A01.D1
D03MA1L  (via drill 0.61)
  Top 0.254: v108.62,170.49 110.84,172.71 110.84,259.7 109.57,260.97 A13.E1
  Bottom 0.254: v108.62,170.49 108.3,170.17 90.52,170.17 89.25,168.9 87.67,168.9 85.76,166.99 79.41,166.99 78.46,167.95 B15.P2 | 107.99,262.24 98.46,262.24 97.51,263.19 A14.E1 | 107.99,262.24 108.94,263.19 A13.E1 | 120.69,262.24 121.64,263.19 A12.E1 | 120.69,262.24 107.99,262.24 | 133.39,262.24 134.34,263.19 A11.E1 | 133.39,262.24 120.69,262.24 | 146.09,262.24 147.04,263.19 A10.E1 | 146.09,262.24 133.39,262.24 | 158.79,262.24 159.74,263.19 A09.E1 | 158.79,262.24 146.09,262.24 | 171.49,262.24 172.44,263.19 A08.E1 | 171.49,262.24 158.79,262.24 | 184.19,262.24 185.14,263.19 A07.E1 | 184.19,262.24 171.49,262.24 | 196.89,262.24 197.84,263.19 A06.E1 | 196.89,262.24 184.19,262.24 | 209.59,262.24 210.54,263.19 A05.E1 | 209.59,262.24 196.89,262.24 | 222.29,262.24 223.24,263.19 A04.E1 | 222.29,262.24 209.59,262.24 | 234.99,262.24 235.94,263.19 A03.E1 | 234.99,262.24 222.29,262.24 | 247.69,262.24 248.64,263.19 A02.E1 | 247.69,262.24 234.99,262.24 | 247.69,262.24 260.39,262.24 261.34,263.19 A01.E1
D03MA2L  (via drill 0.61)
  Top 0.254: v101,150.17 101.32,150.48 101.32,206.36 98.46,209.22 98.46,221.29 98.78,221.6 98.78,254.94 97.19,256.53 A14.H1
  Bottom 0.254: v101,150.17 94.02,150.17 92.75,151.43 91.79,151.43 91.48,151.12 76.24,151.12 75.28,152.07 B15.V2 | 107.99,255.89 108.94,256.85 A13.H1 | 107.99,255.89 98.46,255.89 97.51,256.85 A14.H1 | 120.69,255.89 121.64,256.85 A12.H1 | 120.69,255.89 107.99,255.89 | 133.39,255.89 134.34,256.85 A11.H1 | 133.39,255.89 120.69,255.89 | 146.09,255.89 147.04,256.85 A10.H1 | 146.09,255.89 133.39,255.89 | 158.79,255.89 159.74,256.85 A09.H1 | 158.79,255.89 146.09,255.89 | 171.49,255.89 172.44,256.85 A08.H1 | 171.49,255.89 158.79,255.89 | 184.19,255.89 185.14,256.85 A07.H1 | 184.19,255.89 171.49,255.89 | 196.89,255.89 197.84,256.85 A06.H1 | 196.89,255.89 184.19,255.89 | 209.59,255.89 210.54,256.85 A05.H1 | 209.59,255.89 196.89,255.89 | 222.29,255.89 223.24,256.85 A04.H1 | 222.29,255.89 209.59,255.89 | 234.99,255.89 235.94,256.85 A03.H1 | 234.99,255.89 222.29,255.89 | 247.69,255.89 248.64,256.85 A02.H1 | 247.69,255.89 234.99,255.89 | 247.69,255.89 260.39,255.89 261.34,256.85 A01.H1
D03MA3L  (via drill 0.61)
  Top 0.254: v102.27,127.94 101.95,128.26 101.95,203.19 107.99,209.22 107.99,252.08 106.72,253.35 A13.J1
  Bottom 0.254: v102.27,127.94 101.32,128.89 85.76,128.89 84.81,129.84 C15.E1 | 104.81,252.72 95.29,252.72 94.33,253.67 A14.J1 | 104.81,252.72 105.76,253.67 A13.J1 | 117.51,252.72 118.46,253.67 A12.J1 | 117.51,252.72 104.81,252.72 | 130.21,252.72 131.16,253.67 A11.J1 | 130.21,252.72 117.51,252.72 | 142.91,252.72 143.86,253.67 A10.J1 | 142.91,252.72 130.21,252.72 | 155.61,252.72 156.56,253.67 A09.J1 | 155.61,252.72 142.91,252.72 | 168.31,252.72 169.26,253.67 A08.J1 | 168.31,252.72 155.61,252.72 | 181.01,252.72 181.96,253.67 A07.J1 | 181.01,252.72 168.31,252.72 | 193.71,252.72 194.66,253.67 A06.J1 | 193.71,252.72 181.01,252.72 | 206.41,252.72 207.36,253.67 A05.J1 | 206.41,252.72 193.71,252.72 | 219.11,252.72 220.06,253.67 A04.J1 | 219.11,252.72 206.41,252.72 | 231.81,252.72 232.76,253.67 A03.J1 | 231.81,252.72 219.11,252.72 | 244.51,252.72 245.46,253.67 A02.J1 | 244.51,252.72 231.81,252.72 | 244.51,252.72 257.21,252.72 258.16,253.67 A01.J1
D03MA4L  (via drill 0.61)
  Top 0.254: v102.91,115.24 104.49,116.83 104.49,194.61 106.08,196.2 B13.D1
